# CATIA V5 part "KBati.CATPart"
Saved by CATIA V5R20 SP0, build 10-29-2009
Part number: K_Bati
Bounding box of the stored display mesh (mm): x -20 to 0, y 19.476 to 291.372, z 0 to 547
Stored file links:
  C:\Users\thinkmotion1\Desktop\Khaled_IAO_Pack2\IAO_2010_1392_rragonneau\CATIA_1392_rragonneau\KBati.CATPart
  D:\Documents\Scolaire\MM2\IAO\Squelette\Product1.CATProduct
  C:\Users\thinkmotion1\Desktop\Khaled_IAO_Pack2\IAO_2010_1392_rragonneau\CATIA_1392_rragonneau\KSquelette de base.CATPart
  C:\Users\thinkmotion1\Desktop\Khaled_IAO_Pack2\IAO_2010_1392_rragonneau\CATIA_1392_rragonneau\KSquelette bati.CATPart
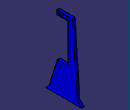
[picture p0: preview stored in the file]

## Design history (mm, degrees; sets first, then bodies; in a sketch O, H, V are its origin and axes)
Set1
  Sketch1 on Plane1, origin (0, 0, 0), H (0, 1, 0), V (0, 0, 1)
    line L1 (291.3723, 0) -> (257.3606, 34.0117)
    point P1 (291.3723, 0)
    point P2 (257.3606, 34.0117)
    line L2 (257.3606, 34.0117) -> (221.4889, 547)
    point P3 (257.3606, 34.0117)
    line L3 (221.4889, 547) -> (103.0337, 547)
    line L4 (103.0337, 547) -> (103.0337, 515)
    line L5 (103.0337, 515) -> (188.51, 515)
    line L6 (188.51, 515) -> (187.343, 225)
    line L7 (187.343, 225) -> (107.8298, 225)
    line L8 (107.8298, 225) -> (45.8462, 26.37)
    line L9 (45.8462, 26.37) -> (19.4762, 0)
    line L10 (19.4762, 0) -> (291.3723, 0)
    point P12 (291.3723, 0)
    reference projected point E1 (125.927, 190) from Point3
    length L4 = 32
    angle L1 L10 = 135
    length L10 = 271.896
    angle L10 L9 = 135
    angle L2 L10 = 94
    distance E1 L7 = 35
    distance L5 L7 = 290
    coincidence: P3 L1, P12 L1, P1 P12, P2 P3, L10 H
    horizontal: L3 H, L5 H, L7 H, L10 H
    vertical: L4 V
Set2
  Plane1: linked copy from another document
  Point1: linked copy from another document
  Plane2: linked copy from another document
  Plane3: linked copy from another document
  Point2: linked copy from another document
  Point3: linked copy from another document
Body1 (main body)
  Pad1: profile Sketch1, direction (-1, 0, 0), length 20
  Sketch2 on Plane1, origin (0, 0, 0), H (0, 1, 0), V (0, 0, 1)
    construction line L1 (125, 531) -> (195, 531)
    line L2 (125, 539) -> (195, 539)
    line L3 (195, 523) -> (125, 523)
    arc A1 centre (195, 531) radius 8 from (195, 539) to (195, 523) cw
    arc A2 centre (125, 531) radius 8 from (125, 523) to (125, 539) cw
    point P3 (125, 539)
    reference intersected line E1 through (0, 0) direction (-1, 0) from Plane2
    reference intersected line E2 through (125, 0) direction (0, 1) from Plane3
    reference projected line E3 (103.0337, 515) -> (188.51, 515) from edge [face of Pad1 from Sketch1.L5 | start face of Pad1]
    length L2 = 70
    distance L3 E3 = 8
    distance L2 L3 = 16
    tangency: A1 L2, A2 L2, A1 L3, A2 L3
    parallelism: L1 E1
    coincidence: P3 E2
  Pocket1: profile Sketch2, direction (-1, 0, 0), through (limit type 3)
  Sketch3 on end face of Pad1, origin (-20, 0, 0), H (0, -1, 0), V (0, 0, 1)
    line L1 (-203, 531) -> (-117, 531)
    point P1 (-203, 531)
    point P2 (-117, 531)
    reference projected line E1 (-125, 539) -> (-195, 539) from edge [end face of Pad1 | face of Pocket1 from Sketch2.L2]
    reference projected arc E2 centre (-125, 531) radius 8 from (-125, 523) to (-125, 539) ccw from edge [face of Pocket1 from Sketch2.A2 | end face of Pad1]
    reference projected arc E3 centre (-195, 531) radius 8 from (-195, 539) to (-195, 523) ccw from edge [face of Pocket1 from Sketch2.A1 | end face of Pad1]
    distance L1 E1 = 8
    distance P2 E2 = 0
    distance P1 E3 = 0
    horizontal: L1 H
  Sketch4 on end face of Pad1, origin (-20, 128.6669, 149.4436), H (0, 1, 0), V (0, 0, -1)
    point P1 (-2.7399, -40.5564)
    reference projected point E1 (-2.7399, -40.5564) from Point3
    distance E1 P1 = 0
  Hole1: placed by Sketch4, at (-20, 125.927, 190) direction (1, 0, 0), diameter 10, through (limit type 3)
  Point4: type Center, Curve edge [face of Pocket1 from Sketch2.A2 | end face of Pad1]
  Point5: type Center, Curve edge [face of Pocket1 from Sketch2.A1 | end face of Pad1]
  Line1: type PtPt, FirstPoint Point4, SecondPoint Point5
